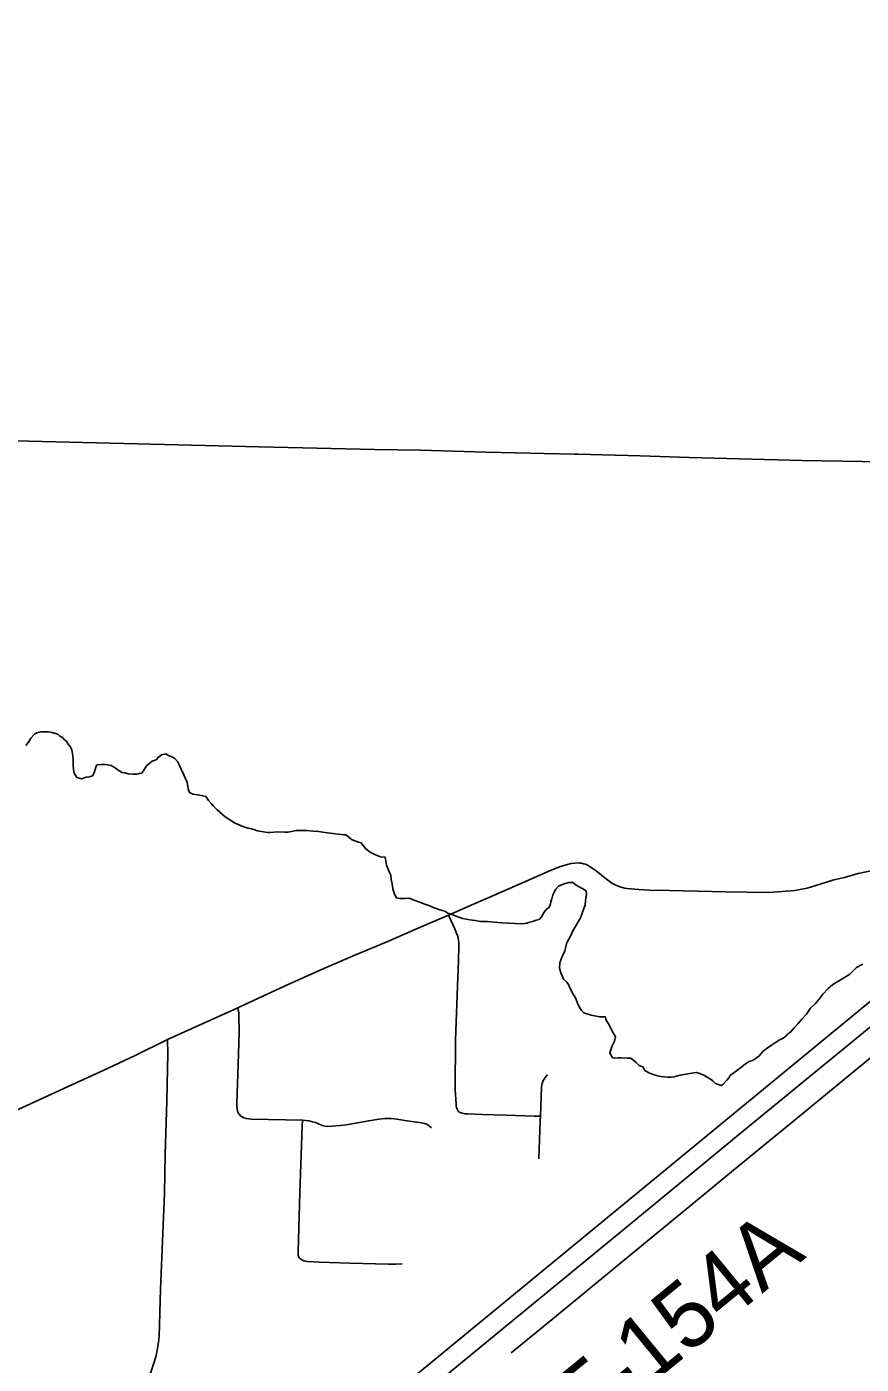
# Model space of a CAD drawing. Extents: x 0 to 34, y 0 to 22.
# Drawn here: x 25.373 to 26.097, y 18.651 to 19.812 of the extents above; entities that cross this region are included whole.
import ezdxf

# ---------------------------------------------------------------- set-up
doc = ezdxf.new("R2010")
doc.units = 0
for name, color, linetype in [('GM_X_Minor_River', 7, 'Continuous'), ('GM_X_Township_Road', 7, 'Continuous'), ('GM_X_Township_Road_Text', 7, 'Continuous'), ('GM_X_US_Route', 7, 'Continuous')]:
    doc.layers.add(name, color=color, linetype=linetype)

msp = doc.modelspace()

# ---------------------------------------------------------------- linework, layer by layer
at = {"layer": 'GM_X_Minor_River'}
for points in [[(25.3719, 19.1884), (25.3747, 19.1921), (25.3763, 19.1947), (25.3794, 19.1981), (25.3813, 19.1992), (25.3848, 19.2002), (25.3867, 19.2002), (25.389, 19.2001), (25.3916, 19.2001), (25.3943, 19.1996), (25.3977, 19.1988), (25.3995, 19.1983), (25.4014, 19.1964), (25.4036, 19.1952), (25.4055, 19.1933), (25.4074, 19.1917), (25.4084, 19.1898), (25.4103, 19.1874), (25.4117, 19.1847), (25.4127, 19.1794), (25.413, 19.176), (25.413, 19.1741), (25.4129, 19.1707), (25.4132, 19.168), (25.4135, 19.1649), (25.4161, 19.1607), (25.4202, 19.1595), (25.4241, 19.1609), (25.4271, 19.1612), (25.4298, 19.1619), (25.431, 19.1645), (25.4326, 19.1694), (25.4334, 19.1717)], [(25.4334, 19.1717), (25.4369, 19.1719), (25.4407, 19.1719), (25.4441, 19.1714), (25.446, 19.171), (25.4493, 19.169), (25.4519, 19.167), (25.4553, 19.165), (25.4576, 19.1646), (25.4606, 19.1638), (25.4648, 19.1636), (25.4682, 19.1636), (25.4701, 19.1639), (25.4724, 19.1642), (25.4767, 19.1709), (25.4814, 19.1746), (25.4848, 19.176), (25.4868, 19.1783), (25.4895, 19.1801), (25.4933, 19.1812), (25.4956, 19.1796), (25.4986, 19.1784), (25.5012, 19.1772), (25.5034, 19.1744), (25.5049, 19.1717), (25.5067, 19.1679), (25.5088, 19.1629), (25.5106, 19.1587), (25.5117, 19.1564), (25.512, 19.1545), (25.5127, 19.1507), (25.5137, 19.1476), (25.5167, 19.146), (25.5228, 19.1451), (25.5281, 19.1442), (25.5303, 19.1407), (25.5329, 19.1376), (25.5347, 19.1357), (25.5377, 19.1326), (25.5447, 19.1263), (25.553, 19.1212), (25.5601, 19.1179), (25.5643, 19.1167), (25.5665, 19.1163), (25.5695, 19.1154), (25.5729, 19.1142), (25.5816, 19.1128), (25.5835, 19.1128), (25.5904, 19.1134), (25.5965, 19.1132), (25.5991, 19.1131), (25.601, 19.1135), (25.6064, 19.1145), (25.6155, 19.1146), (25.6212, 19.1141), (25.6257, 19.1136), (25.6314, 19.1127), (25.6359, 19.1122), (25.6405, 19.1117), (25.6435, 19.1113), (25.6477, 19.1108), (25.6496, 19.1107), (25.6544, 19.1068), (25.6604, 19.1044), (25.6627, 19.1039), (25.6667, 19.0985), (25.6705, 19.0958), (25.6753, 19.0934), (25.6795, 19.0917), (25.6837, 19.0913), (25.6846, 19.0844), (25.6871, 19.0786), (25.6886, 19.0759), (25.6889, 19.0721), (25.6895, 19.0683), (25.6902, 19.0638), (25.6916, 19.0592), (25.6934, 19.0561), (25.6964, 19.0556), (25.701, 19.0555), (25.7044, 19.0558), (25.7093, 19.0538), (25.7142, 19.0521), (25.718, 19.0505), (25.7206, 19.0497), (25.7229, 19.0489), (25.7251, 19.0477), (25.7277, 19.0468), (25.73, 19.046), (25.733, 19.0452), (25.7353, 19.0444), (25.7379, 19.0428), (25.7413, 19.0416), (25.7451, 19.0403), (25.7507, 19.0383), (25.7571, 19.037), (25.7617, 19.0365), (25.7662, 19.0356), (25.7723, 19.0355), (25.7783, 19.0349), (25.7852, 19.0344)], [(25.7852, 19.0344), (25.8022, 19.0336), (25.8045, 19.0339), (25.8064, 19.0342), (25.8091, 19.0349), (25.8114, 19.0356), (25.8145, 19.0367), (25.8172, 19.0374), (25.8191, 19.0396), (25.8215, 19.0437), (25.8238, 19.0467), (25.8258, 19.0478), (25.827, 19.0508), (25.8274, 19.0527), (25.8282, 19.0553), (25.8291, 19.0587), (25.8303, 19.061), (25.8315, 19.0636), (25.8338, 19.0662), (25.8388, 19.0683), (25.843, 19.0694), (25.8464, 19.0693), (25.8502, 19.0665), (25.855, 19.0638), (25.858, 19.0622), (25.8583, 19.0591), (25.8575, 19.0542), (25.857, 19.0497), (25.8562, 19.0478), (25.8557, 19.0459), (25.8545, 19.0429), (25.8529, 19.0387), (25.8461, 19.0268), (25.8441, 19.0223), (25.8417, 19.0181), (25.8409, 19.0163), (25.8401, 19.0125), (25.8393, 19.0102), (25.838, 19.0068), (25.8368, 19.0046), (25.836, 19.0019), (25.8352, 18.9997), (25.8347, 18.9951), (25.8361, 18.9909), (25.8383, 18.9856), (25.8412, 18.9828), (25.8427, 18.9809), (25.8441, 18.9774), (25.8467, 18.9724), (25.8489, 18.9686), (25.8503, 18.9647), (25.8521, 18.9609), (25.8539, 18.9582), (25.8558, 18.9563), (25.8622, 18.9542), (25.8697, 18.9529), (25.8747, 18.9527), (25.875, 18.9505), (25.8783, 18.9454), (25.8804, 18.9404), (25.8823, 18.9374), (25.8833, 18.9354), (25.8825, 18.9316), (25.8809, 18.9283), (25.8797, 18.9249), (25.8785, 18.9219), (25.8806, 18.9176), (25.8825, 18.9168), (25.8856, 18.9171), (25.8882, 18.9171), (25.8935, 18.9169), (25.8966, 18.9169), (25.9014, 18.9133), (25.904, 18.9106), (25.907, 18.9094), (25.9088, 18.9063), (25.9122, 18.9043), (25.9156, 18.9031), (25.919, 18.9019), (25.9228, 18.901), (25.9284, 18.9005), (25.9315, 18.9004), (25.9341, 18.9007), (25.9364, 18.9014), (25.9395, 18.9021), (25.9513, 18.9041), (25.9536, 18.9044), (25.9566, 18.9036), (25.96, 18.9023), (25.9623, 18.9008), (25.9649, 18.8992), (25.9679, 18.8972), (25.9701, 18.8949), (25.975, 18.8932), (25.9769, 18.8943), (25.98, 18.8977), (25.9816, 18.8999), (25.9832, 18.9021), (25.9859, 18.9043), (25.9894, 18.9069), (25.9929, 18.9095)], [(25.9929, 18.9095), (25.9963, 18.9121), (25.9998, 18.9142), (26.0021, 18.9149), (26.004, 18.916), (26.0064, 18.9175), (26.0083, 18.9193), (26.011, 18.9223), (26.0141, 18.9249), (26.0188, 18.9282), (26.0223, 18.9304), (26.0253, 18.9326), (26.0288, 18.9344), (26.0311, 18.9359), (26.0327, 18.9377), (26.0354, 18.9399), (26.0385, 18.9433), (26.0417, 18.9466), (26.0452, 18.9511), (26.0491, 18.9552), (26.0526, 18.9604), (26.0565, 18.9641), (26.0597, 18.9678), (26.0632, 18.9726), (26.0675, 18.9771), (26.0718, 18.9808), (26.0845, 18.9884), (26.0868, 18.9899), (26.0887, 18.9918), (26.0926, 18.9955), (26.098, 18.9984)]]:
    msp.add_lwpolyline(points, dxfattribs=at)
at = {"layer": 'GM_X_Township_Road'}
for points in [[(24.8748, 19.4645), (24.8901, 19.4643), (24.9274, 19.4638), (24.9852, 19.4624), (25.0547, 19.4604), (25.138, 19.4586), (25.1964, 19.4572), (25.2586, 19.4557), (25.3325, 19.4536), (25.3623, 19.4529), (25.445, 19.4507), (25.5742, 19.4477), (25.6743, 19.4453), (25.7141, 19.4446), (25.7713, 19.4431), (25.8216, 19.4419), (25.8479, 19.4412)], [(25.8479, 19.4412), (25.8508, 19.4411), (25.9049, 19.4397), (25.9477, 19.4384), (25.9906, 19.4372)], [(25.9906, 19.4372), (26.0235, 19.4363), (26.0453, 19.4358), (26.1844, 19.4333), (26.1862, 19.4332), (26.1881, 19.433), (26.1899, 19.4326), (26.1924, 19.4315), (26.1936, 19.4309), (26.1956, 19.4296)], [(25.7386, 19.0411), (25.7601, 19.0506), (25.7795, 19.0591), (25.8034, 19.0695), (25.825, 19.0791), (25.8348, 19.083), (25.8406, 19.0849), (25.8448, 19.0858), (25.8482, 19.0863), (25.8502, 19.0864), (25.8521, 19.0863), (25.8538, 19.0861), (25.8556, 19.0857), (25.8573, 19.0852), (25.8591, 19.0844), (25.8611, 19.0834), (25.8631, 19.082), (25.8665, 19.0795), (25.8756, 19.0722), (25.8803, 19.0689), (25.8831, 19.0674), (25.8856, 19.0663), (25.8883, 19.0653), (25.8911, 19.0646), (25.8934, 19.0642), (25.8968, 19.0638), (25.9035, 19.0632), (25.9129, 19.0627), (25.9303, 19.0625), (25.9788, 19.0614), (26.0164, 19.0607), (26.0389, 19.0626), (26.0498, 19.0646), (26.0608, 19.0679), (26.0727, 19.0717), (26.082, 19.0739), (26.094, 19.0772), (26.112, 19.081)], [(25.5558, 18.9607), (25.5575, 18.9615), (25.5969, 18.9798), (25.6305, 18.9947), (25.6573, 19.0062), (25.6865, 19.0186), (25.7128, 19.03), (25.7386, 19.0411)], [(25.7475, 18.8703), (25.747, 18.8708), (25.7463, 18.872), (25.7459, 18.8727), (25.7457, 18.8734), (25.7455, 18.8742), (25.7453, 18.8754), (25.7451, 18.8771), (25.7443, 18.8896), (25.7445, 18.9326), (25.7465, 18.9873), (25.7471, 19.0009), (25.7476, 19.0146), (25.7475, 19.0172), (25.7472, 19.0193), (25.7469, 19.0215), (25.7464, 19.0234), (25.7453, 19.026), (25.744, 19.0292), (25.7386, 19.0411)], [(25.4947, 18.9331), (25.521, 18.9449), (25.5558, 18.9607)], [(25.5558, 18.9607), (25.5564, 18.958), (25.5566, 18.9561), (25.5567, 18.9538), (25.5568, 18.9403), (25.5563, 18.9204), (25.5549, 18.8776), (25.5549, 18.8758), (25.5552, 18.8728), (25.5555, 18.8711), (25.556, 18.8696), (25.5568, 18.8682), (25.558, 18.867), (25.5594, 18.8659), (25.5611, 18.8651), (25.5632, 18.8645), (25.5653, 18.8642), (25.5675, 18.864), (25.6118, 18.8632)], [(25.1096, 18.7944), (25.1106, 18.7945), (25.1255, 18.7964), (25.1483, 18.7994), (25.171, 18.8028), (25.1858, 18.8053), (25.1968, 18.8075), (25.2083, 18.8104), (25.2203, 18.8138), (25.2321, 18.8177), (25.2467, 18.8231), (25.3078, 18.8478), (25.3388, 18.8608), (25.3689, 18.8742), (25.4085, 18.8922), (25.439, 18.9063), (25.466, 18.9191), (25.4947, 18.9331)], [(25.4631, 18.5934), (25.467, 18.6052), (25.4702, 18.6159), (25.4761, 18.6336), (25.4799, 18.6435), (25.4831, 18.6529), (25.4849, 18.6588), (25.4855, 18.6618), (25.4864, 18.6667), (25.4872, 18.6726), (25.4874, 18.6757), (25.4887, 18.7164), (25.492, 18.7997), (25.4928, 18.8333), (25.4941, 18.8799), (25.4947, 18.9079), (25.4949, 18.9203), (25.4947, 18.9331)], [(25.793, 18.661), (25.8289, 18.6906), (25.911, 18.7582), (25.948, 18.7885), (25.9907, 18.8237), (26.0348, 18.86), (26.1144, 18.9252)], [(25.8182, 18.8665), (25.8185, 18.8754), (25.8192, 18.8919), (25.8196, 18.8941), (25.8201, 18.8958), (25.8207, 18.8974), (25.8214, 18.8988), (25.8223, 18.9002), (25.8243, 18.9026)], [(25.7475, 18.8703), (25.7486, 18.8697), (25.7494, 18.8694), (25.7504, 18.8691), (25.7515, 18.8689), (25.7527, 18.8687), (25.7551, 18.8686), (25.7681, 18.8681), (25.7886, 18.8674), (25.8127, 18.8666), (25.8182, 18.8665)], [(25.6984, 18.7385), (25.6927, 18.7382), (25.6865, 18.738), (25.6529, 18.7391), (25.6267, 18.7398), (25.6158, 18.7405), (25.6144, 18.7407), (25.6131, 18.7411), (25.6119, 18.7416), (25.6108, 18.7422), (25.61, 18.7428), (25.6093, 18.7434), (25.6088, 18.7443), (25.6084, 18.7451), (25.6081, 18.746), (25.608, 18.7472), (25.6081, 18.7492), (25.6096, 18.8001), (25.6116, 18.8579), (25.6118, 18.8632)], [(25.6118, 18.8632), (25.6174, 18.8624), (25.6205, 18.8618), (25.623, 18.861), (25.6284, 18.8589), (25.6301, 18.8583), (25.6316, 18.858), (25.6333, 18.8577), (25.6375, 18.8578), (25.6443, 18.8584), (25.6498, 18.8592), (25.6693, 18.8626), (25.678, 18.864), (25.6836, 18.8645), (25.6887, 18.8645), (25.6937, 18.8641), (25.7005, 18.8628), (25.7152, 18.8609), (25.7177, 18.8603), (25.7196, 18.8596), (25.7218, 18.8581), (25.7238, 18.8565)], [(25.8168, 18.8295), (25.8181, 18.8624), (25.8182, 18.8665)]]:
    msp.add_lwpolyline(points, dxfattribs=at)
at = {"layer": 'GM_X_US_Route'}
for points in [[(25.3816, 18.3719), (25.5554, 18.5144), (26.23, 19.0696), (26.7673, 19.5121), (26.796, 19.5364), (26.9031, 19.6225), (26.9577, 19.6666), (27.0038, 19.7051), (27.0357, 19.7314), (27.0557, 19.7465), (27.1054, 19.7879), (27.1346, 19.8123)], [(25.3961, 18.3619), (25.4617, 18.4159), (25.5194, 18.4631), (25.5655, 18.5011), (25.7912, 18.6867), (25.8911, 18.7688), (25.9996, 18.8582), (26.1209, 18.9575)]]:
    msp.add_lwpolyline(points, dxfattribs=at)

# ---------------------------------------------------------------- texts
at = {"layer": 'GM_X_Township_Road_Text'}
msp.add_text('T-154A', height=0.05682, rotation=39.335, dxfattribs=at).set_placement((25.857, 18.5865))

doc.saveas('drawing.dxf')
